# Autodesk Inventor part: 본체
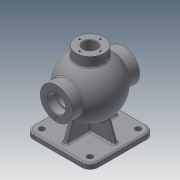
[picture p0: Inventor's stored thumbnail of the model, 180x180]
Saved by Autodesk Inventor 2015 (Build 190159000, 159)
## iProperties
Created: 2025-08
Part Number: 본체
Material: 일반
Document SubType Name: Modeling
Designer: user
Density: 1 g/cm^3
Appearance: 기본값
Author: user
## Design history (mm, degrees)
sketch "스케치1"
  geometry: L1 (-62.5, -62.5)-(62.5, -62.5); L2 (62.5, -62.5)-(62.5, 62.5); L3 (62.5, 62.5)-(-62.5, 62.5); L4 (-62.5, 62.5)-(-62.5, -62.5); L5 (-62.5, -62.5)-(62.5, 62.5); L6 (62.5, -62.5)-(-62.5, 62.5); 1 further point
  constraints: 12 end point, 2 midpoint, 2 parallel, 1 horizontal, 1 perpendicular
  dimensions: "d0" = 125 distance of L3.end L2.end; "d1" = 125 distance of L2.end L1.end
extrude "돌출1" new body sketch "스케치1" distance "d2" = 10; taper "d3" = 0 deg
fillet "모깎기1" dims "d4" = 16
hole "구멍1" diameter "d7" = 11; stored, may be unused: countersink angle "d11" = 90 deg, drill point angle "d13" = 118 deg; dims "d5" = 16, "d6" = 16, "d8" = 6, "d9" = 4, "d10" = 2, "d12" = 8
sketch "스케치2"
  geometry: L1 (-54, 85)-(54, 85); A1 r 54 centre (0, 85) between (54, 85) and (-54, 85); 2 further points
  constraints: 2 end point, 2 point on circle, 1 centre point, 1 horizontal, 1 midpoint, 1 vertical alignment
  dimensions: "d20" = 108 diameter of A1; "d21" = 85 distance of point (0, 0) A1.centre; "d22" = 108 distance of L1.start L1.end
revolve "회전1" sketch "스케치2" stored, may be unused: angle "d23" = 90 deg
sketch "스케치3"
  geometry: L1 (-44, 85)-(44, 85); C1 r 54 at (0, 85) reference; A1 r 44 centre (0, 85) between (44, 85) and (-44, 85); 1 further point
  constraints: 2 end point, 2 point on circle, 1 centre point, 1 coincident, 1 horizontal
  dimensions: "d24" = 88 diameter of A1; "d25" = 88 distance of L1.start L1.end
revolve "회전2" sketch "스케치3" stored, may be unused: angle "d26" = 90 deg
sketch "스케치4"
  geometry: L1 (-46.5, 62.5)-(46.5, 62.5) reference; L2 (62.5, 46.5)-(62.5, -46.5) reference; L3 (46.5, -62.5)-(-46.5, -62.5) reference; L4 (-62.5, -46.5)-(-62.5, 46.5) reference; L5 (4, 50.5)-(4, -50.5); L6 (4, -50.5)-(-4, -50.5); L7 (-4, -50.5)-(-4, 50.5); L8 (-4, 50.5)-(4, 50.5); L9 (4, 50.5)-(-4, -50.5); L10 (4, -50.5)-(-4, 50.5); L11 (50.5, -4)-(-50.5, -4); L12 (-50.5, -4)-(-50.5, 4); L13 (-50.5, 4)-(50.5, 4); L14 (50.5, 4)-(50.5, -4); L15 (50.5, -4)-(-50.5, 4); L16 (-50.5, -4)-(50.5, 4); C1 r 5.5 at (46.5, 46.5) reference; C2 r 5.5 at (46.5, -46.5) reference; C3 r 5.5 at (-46.5, 46.5) reference; C4 r 5.5 at (-46.5, -46.5) reference; A1 r 16 centre (-46.5, 46.5) between (-46.5, 62.5) and (-62.5, 46.5) reference; A2 r 16 centre (46.5, 46.5) between (62.5, 46.5) and (46.5, 62.5) reference; A3 r 16 centre (46.5, -46.5) between (46.5, -62.5) and (62.5, -46.5) reference; A4 r 16 centre (-46.5, -46.5) between (-62.5, -46.5) and (-46.5, -62.5) reference; 1 further point
  constraints: 24 end point, 4 midpoint, 4 parallel, 2 perpendicular, 1 horizontal, 1 vertical
  dimensions: "d27" = 101 distance of L5.start L5.end; "d28" = 8 distance of L5.end L6.end; "d29" = 101 distance of L11.start L11.end; "d30" = 8 distance of L11.end L12.end
extrude "돌출2" join sketch "스케치4" stored distance "d31" = 10; taper "d32" = 0 deg
feature "면 기울기1" dims angle "d33" = 20 deg
node "작업 평면1"
sketch "스케치5"
  geometry: C1 r 27 at (0, 0); 1 further point
  constraints: 1 centre point, 1 coincident
  dimensions: "d35" = 54 diameter of C1
extrude "돌출3" join sketch "스케치5" stored distance "d36" = 10; taper "d37" = 0 deg
node "작업 평면2"
sketch "스케치6"
  geometry: C1 r 31 at (0, 85); A1 r 54 centre (0, 85) between (37.385, 46.034) and (-37.385, 46.034) reference; 1 further point
  constraints: 1 centre point, 1 coincident
  dimensions: "d39" = 62 diameter of C1
extrude "돌출4" join sketch "스케치6" stored distance "d40" = 10; taper "d41" = 0 deg
hole "구멍2" diameter "d44" = 30; stored, may be unused: countersink angle "d48" = 90 deg, drill point angle "d50" = 0 deg; dims "d42" = 10, "d43" = 10, "d45" = 6, "d46" = 35, "d47" = 16, "d49" = 8
hole "구멍3" diameter "d53" = 26; stored, may be unused: countersink angle "d57" = 90 deg, drill point angle "d59" = 0 deg; dims "d54" = 6, "d55" = 35, "d56" = 16, "d58" = 50, "d60" = 10, "d61" = 10
sketch "스케치7"
  geometry: L1 (0, 0)-(0, 24); C1 r 15 at (0, 0) reference; 1 further point
  constraints: 2 end point, 1 vertical
  dimensions: "d62" = 24 distance of L1.start L1.end
hole "구멍4" sketch "스케치7" at (0, 24) diameter "d63" = 3.242; stored, may be unused: countersink angle "d67" = 90 deg, drill point angle "d69" = 118 deg; dims "d64" = 12, "d65" = 35, "d66" = 16, "d68" = 15
sketch "스케치8"
  geometry: L1 (0, 0)-(20, 0)
  constraints: 2 end point, 1 horizontal
  dimensions: "d73" = 20 distance of L1.start L1.end
hole "구멍5" sketch "스케치8" at (20, 0) diameter "d74" = 3.242; stored, may be unused: countersink angle "d78" = 90 deg, drill point angle "d80" = 118 deg; dims "d75" = 9, "d76" = 35, "d77" = 16, "d79" = 11
chamfer "모따기1" distance "d84" = 1; stored, may be unused: second distance "d85" = 2, angle "d86" = 45 deg
fillet "모깎기2" dims "d87" = 0.6
fillet "모깎기3" dims "d88" = 3
fillet "모깎기4" dims "d89" = 3
fillet "모깎기5" dims "d90" = 3
fillet "모깎기6" dims "d91" = 3
fillet "모깎기7" dims "d92" = 3
sketch "스케치9"
  geometry: L1 (50, 110.621)-(49.026, 109) reference; L2 (49.026, 109)-(50, 107.379) reference; L3 (50, 107.379)-(65, 107.379) reference; L4 (65, 107.379)-(65, 103.5) reference; L5 (65, 103.5)-(64, 102.5) reference; L6 (64, 102.5)-(49.6, 102.5) reference; L7 (49, 101.9)-(49, 100) reference; L8 (49, 100)-(41.364, 100) reference; L9 (13, 127.036)-(13, 149) reference; L10 (13, 149)-(14, 150) reference; L11 (14, 150)-(18.379, 150) reference; L12 (18.379, 150)-(18.379, 139) reference; L13 (18.379, 139)-(20, 138.026) reference; L14 (20, 138.026)-(21.621, 139) reference; L15 (21.621, 139)-(21.621, 150) reference; L16 (21.621, 150)-(27, 150) reference; L17 (27, 150)-(27, 133.466) reference; L18 (45.749, 116)-(65, 116) reference; L19 (65, 116)-(65, 110.621) reference; L20 (65, 110.621)-(50, 110.621) reference; L21 (-50, 59.379)-(-49.026, 61) reference; L22 (-49.026, 61)-(-50, 62.621) reference; L23 (-50, 62.621)-(-65, 62.621) reference; L24 (-65, 62.621)-(-65, 66.5) reference; L25 (-65, 66.5)-(-64, 67.5) reference; L26 (-64, 67.5)-(-49.6, 67.5) reference; L27 (-49, 68.1)-(-49, 70) reference; L28 (-49, 70)-(-41.364, 70) reference; L29 (41.364, 70)-(49, 70) reference; L30 (49, 70)-(49, 68.1) reference; L31 (49.6, 67.5)-(64, 67.5) reference; L32 (64, 67.5)-(65, 66.5) reference; L33 (65, 66.5)-(65, 62.621) reference; L34 (65, 62.621)-(50, 62.621) reference; L35 (50, 62.621)-(49.026, 61) reference; L36 (49.026, 61)-(50, 59.379) reference; L37 (50, 59.379)-(65, 59.379) reference; L38 (65, 59.379)-(65, 54) reference; L39 (65, 54)-(45.749, 54) reference; L40 (38.041, 44.231)-(49.782, 11.974) reference; L41 (52.601, 10)-(59.5, 10) reference; L42 (62.5, 7)-(62.5, 0) reference; L43 (62.5, 0)-(-62.5, 0) reference; L44 (-62.5, 0)-(-62.5, 7) reference; L45 (-59.5, 10)-(-52.601, 10) reference; L46 (-49.782, 11.974)-(-38.041, 44.231) reference; L47 (-45.749, 54)-(-65, 54) reference; L48 (-65, 54)-(-65, 59.379) reference; L49 (-65, 59.379)-(-50, 59.379) reference; L50 (-49.026, 109)-(-50, 110.621) reference; L51 (-50, 110.621)-(-65, 110.621) reference; L52 (-65, 110.621)-(-65, 116) reference; L53 (-65, 116)-(-45.749, 116) reference; L54 (-27, 133.466)-(-27, 150) reference; L55 (-27, 150)-(-21.621, 150) reference; L56 (-21.621, 150)-(-21.621, 139) reference; L57 (-21.621, 139)-(-20, 138.026) reference; L58 (-20, 138.026)-(-18.379, 139) reference; L59 (-18.379, 139)-(-18.379, 150) reference; L60 (-18.379, 150)-(-14, 150) reference; L61 (-14, 150)-(-13, 149) reference; L62 (-13, 149)-(-13, 127.036) reference; L63 (-41.364, 100)-(-49, 100) reference; L64 (-49, 100)-(-49, 101.9) reference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; A1 r 0.6 centre (49.6, 101.9) between (49.6, 102.5) and (49, 101.9) reference; A2 r 44 centre (0, 85) between (41.364, 100) and (13, 127.036) reference; A3 r 3 centre (30, 133.466) between (27, 133.466) and (28.421, 130.916) reference; A4 r 54 centre (0, 85) between (43.341, 117.211) and (28.421, 130.916) reference; A5 r 3 centre (45.749, 119) between (43.341, 117.211) and (45.749, 116) reference; A6 r 0.6 centre (-49.6, 68.1) between (-49.6, 67.5) and (-49, 68.1) reference; A7 r 44 centre (0, 85) between (-41.364, 70) and (41.364, 70) reference; A8 r 0.6 centre (49.6, 68.1) between (49, 68.1) and (49.6, 67.5) reference; A9 r 3 centre (45.749, 51) between (45.749, 54) and (43.341, 52.789) reference; A10 r 54 centre (0, 85) between (38.709, 47.349) and (43.341, 52.789) reference; A11 r 3 centre (40.86, 45.257) between (38.709, 47.349) and (38.041, 44.231) reference; A12 r 3 centre (52.601, 13) between (49.782, 11.974) and (52.601, 10) reference; A13 r 3 centre (59.5, 7) between (62.5, 7) and (59.5, 10) reference; A14 r 3 centre (-59.5, 7) between (-59.5, 10) and (-62.5, 7) reference; A15 r 3 centre (-52.601, 13) between (-52.601, 10) and (-49.782, 11.974) reference; A16 r 3 centre (-40.86, 45.257) between (-38.041, 44.231) and (-38.709, 47.349) reference; A17 r 54 centre (0, 85) between (-43.341, 52.789) and (-38.709, 47.349) reference; A18 r 3 centre (-45.749, 51) between (-43.341, 52.789) and (-45.749, 54) reference; A19 r 3 centre (-45.749, 119) between (-45.749, 116) and (-43.341, 117.211) reference; A20 r 54 centre (0, 85) between (-28.421, 130.916) and (-43.341, 117.211) reference; A21 r 3 centre (-30, 133.466) between (-28.421, 130.916) and (-27, 133.466) reference; A22 r 44 centre (0, 85) between (-13, 127.036) and (-41.364, 100) reference; A23 r 0.6 centre (-49.6, 101.9) between (-49, 101.9) and (-49.6, 102.5) reference; 2 further points
  constraints: 1 vertical alignment, 1 other
  dimensions: "d93" = 9 distance from line of L55 point (0, 141)
feature "엠보싱1" sketch "스케치9" dims "d0" = 125, "d1" = 125, "d94" = 0.5, "d95" = 0
node "솔리드1"
pattern_linear "직사각형 패턴1" dims "d16" = 93, "d19" = 93
mirror "대칭1"
pattern_circular "원형 패턴1" dims angle "d71" = 360 deg
mirror "대칭2"
pattern_circular "원형 패턴2" dims angle "d82" = 360 deg
node "절단 모서리 투영1"
node "절단 모서리 투영2"
other parameters: "d38" = -65
